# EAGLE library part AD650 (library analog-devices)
AD650 - Voltage-to-Frequency and Frequency-to-Voltage Converter Source: http://www.analog.com/en/prod/0,,760_794_AD650,00.html
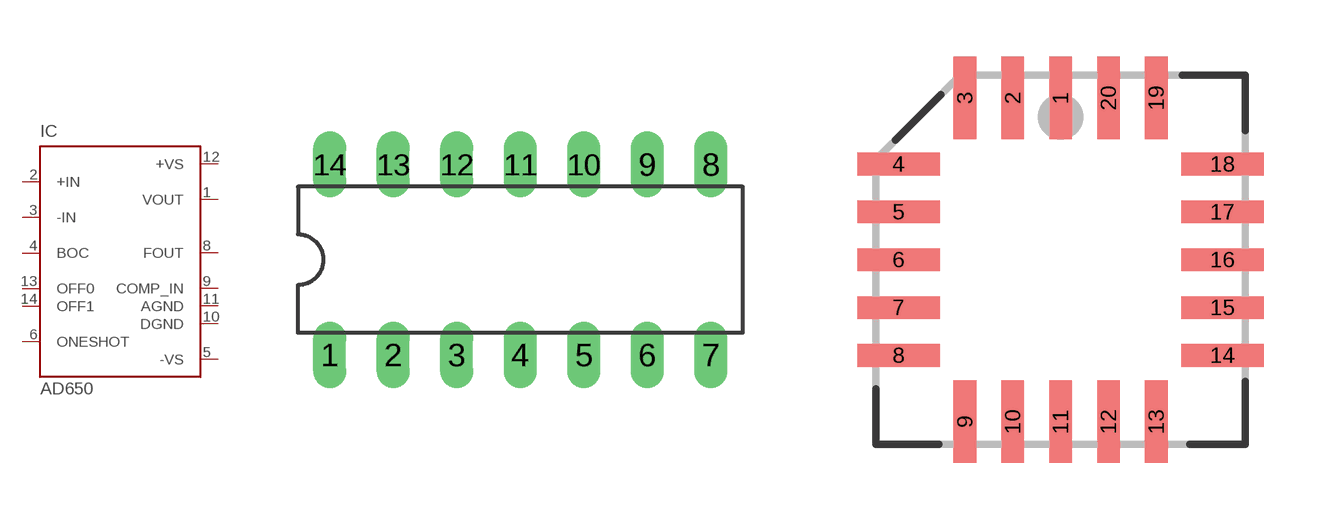
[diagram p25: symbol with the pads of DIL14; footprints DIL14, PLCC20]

Designator prefix IC

## AD650N (MF: ALTERA CORPORATION; MPN: AD650KN; OC_FARNELL: 1464457; OC_NEWARK: 05F7159)  [DIL14]
1  VOUT  out
2  +IN  in
3  -IN  in
4  BOC  pas
5  -VS  in
6  ONESHOT  pas
8  FOUT  out
9  COMP_IN  in
10  DGND  in
11  AGND  in
12  +VS  in
13  OFF0  in
14  OFF1  in

## AD650P (OC_FARNELL: unknown; OC_NEWARK: unknown)  [PLCC20]
2  VOUT  out
3  +IN  in
4  -IN  in
6  BOC  pas
8  -VS  in
9  ONESHOT  pas
12  FOUT  out
13  COMP_IN  in
14  DGND  in
16  AGND  in
18  +VS  in
19  OFF0  in
20  OFF1  in

## Footprint DIL14 (pad centres in mm)
Dual In Line Package
drill 0.813 long: 1 -7.62,-3.81; 2 -5.08,-3.81; 3 -2.54,-3.81; 4 0,-3.81; 5 2.54,-3.81; 6 5.08,-3.81; 7 7.62,-3.81; 8 7.62,3.81; 9 5.08,3.81; 10 2.54,3.81; 11 0,3.81; 12 -2.54,3.81; 13 -5.08,3.81; 14 -7.62,3.81

## Footprint PLCC20 (pad centres in mm)
Plastic Leaded Chip Carrier IPC standard
smd 0.6 x 2.2: 1 0,4.3; 2 -1.27,4.3; 3 -2.54,4.3; 9 -2.54,-4.3; 10 -1.27,-4.3; 11 0,-4.3; 12 1.27,-4.3; 13 2.54,-4.3; 19 2.54,4.3; 20 1.27,4.3
smd 2.2 x 0.6: 4 -4.3,2.54; 5 -4.3,1.27; 6 -4.3,0; 7 -4.3,-1.27; 8 -4.3,-2.54; 14 4.3,-2.54; 15 4.3,-1.27; 16 4.3,0; 17 4.3,1.27; 18 4.3,2.54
